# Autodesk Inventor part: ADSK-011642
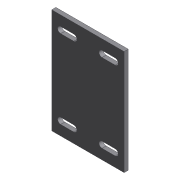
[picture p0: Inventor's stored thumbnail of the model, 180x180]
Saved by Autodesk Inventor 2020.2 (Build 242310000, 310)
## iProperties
Created: 2000-02
Part Number: ADSK-011642
Material: Pearson HRS
Document SubType Name: Modeling
Designer: sspink
Density: 7.83 g/cm^3
Appearance: Métal - Acier
Mass: 705.712 g
Surface Area: 347.176 cm^2
Volume: 90.1292 cm^3
Control State: 0
Master: False
Checked Out: False
Shininess: 0.0
Length Units: 11269
Angle Units: 11279
Time Units: 11290
Mass Units: 11283
Length Display Precision: 3
Angle Display Precision: 2
Compacted: True
Cutlength: 6
Material Desc: FLAT,HRS,0.250X04.000
Material_Number: A084338
Dimensions: 152x6x105 mm
Mass: 0,706 kg
VLT_Material: Pearson HRS
Density: 0.0
Volumn: 0.0
Area: 0.0
PropertySet Name: Model Information
Author: sspink
Revision Number: -
Title: ADSK-011642
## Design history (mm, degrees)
node "Solide1"
  node "Extrusion1" dims "d2" = 6, "d3" = 0
  node "Extrusion2" dims "d8" = 25.4, "d9" = 0
  node "Chamfer1" dims "d10" = 5.95312, "d11" = 42 deg, "d19" = 5.95312
sketch "Sketch1"
  geometry: L1 (-52.5, -76)-(52.5, -76); L2 (52.5, -76)-(52.5, 76); L3 (52.5, 76)-(-52.5, 76); L4 (-52.5, 76)-(-52.5, -76); 3 further points
  constraints: 8 end point, 2 midpoint, 2 parallel, 1 horizontal, 1 horizontal alignment, 1 perpendicular, 1 vertical alignment
  dimensions: "d0" = 152 distance between parallel lines of L1 L3; "d1" = 105 distance between parallel lines of L2 L4
sketch "Sketch2"
  geometry: L1 (-20.5, 52.5)-(-39.5, 52.5); L2 (-39.5, 52.5)-(-39.5, 61.5); L3 (-39.5, 61.5)-(-20.5, 61.5); L4 (-20.5, 61.5)-(-20.5, 52.5); L5 (-20.5, 57)-(-39.5, 57); L6 (30, -57)-(-30, -57); L7 (-30, -57)-(-30, 57); L8 (-30, 57)-(30, 57); L9 (30, 57)-(30, -57); L10 (30, -57)-(-30, 57); L11 (-30, -57)-(30, 57); L12 (39.5, 52.5)-(20.5, 52.5); L13 (20.5, 52.5)-(20.5, 61.5); L14 (20.5, 61.5)-(39.5, 61.5); L15 (39.5, 61.5)-(39.5, 52.5); L16 (39.5, 57)-(20.5, 57); L17 (-20.5, -61.5)-(-39.5, -61.5); L18 (-39.5, -61.5)-(-39.5, -52.5); L19 (-39.5, -52.5)-(-20.5, -52.5); L20 (-20.5, -52.5)-(-20.5, -61.5); L21 (-20.5, -57)-(-39.5, -57); L22 (39.5, -61.5)-(20.5, -61.5); L23 (20.5, -61.5)-(20.5, -52.5); L24 (20.5, -52.5)-(39.5, -52.5); L25 (39.5, -52.5)-(39.5, -61.5); L26 (39.5, -57)-(20.5, -57); A1 r 4.5 centre (-39.5, 57) between (-39.5, 61.5) and (-39.5, 52.5); A2 r 4.5 centre (-20.5, 57) between (-20.5, 52.5) and (-20.5, 61.5); A3 r 4.5 centre (20.5, 57) between (20.5, 61.5) and (20.5, 52.5); A4 r 4.5 centre (39.5, 57) between (39.5, 52.5) and (39.5, 61.5); A5 r 4.5 centre (-39.5, -57) between (-39.5, -52.5) and (-39.5, -61.5); A6 r 4.5 centre (-20.5, -57) between (-20.5, -61.5) and (-20.5, -52.5); A7 r 4.5 centre (20.5, -57) between (20.5, -52.5) and (20.5, -61.5); A8 r 4.5 centre (39.5, -57) between (39.5, -61.5) and (39.5, -52.5); 1 further point
  constraints: 52 end point, 16 point on circle, 10 parallel, 9 horizontal, 8 centre point, 8 tangent, 6 midpoint, 5 perpendicular
  dimensions: "d5" = 9 distance of L3.end L1.start; "d7" = 19 distance of L2.end L3.end; "d20" = 114 distance of L8.end L6.start; "d21" = 60 distance of L7.end L8.end; "d22" = 9 distance of L14.end L12.start (= d5); "d23" = 19 distance of L13.end L14.end; "d24" = 9 distance of L19.end L17.start (= d5); "d25" = 19 distance of L18.end L19.end; "d26" = 9 distance of L24.end L22.start (= d5); "d27" = 19 distance of L23.end L24.end
workpoint "Arbeitspunkt1"
workpoint "Arbeitspunkt2"
workpoint "Arbeitspunkt3"
workpoint "Arbeitspunkt4"
workaxis "Arbeitsachse3"
workaxis "Arbeitsachse4"
workaxis "Arbeitsachse5"
workaxis "Arbeitsachse6"
node "Corps solides"
node "Corps surfaciques"
